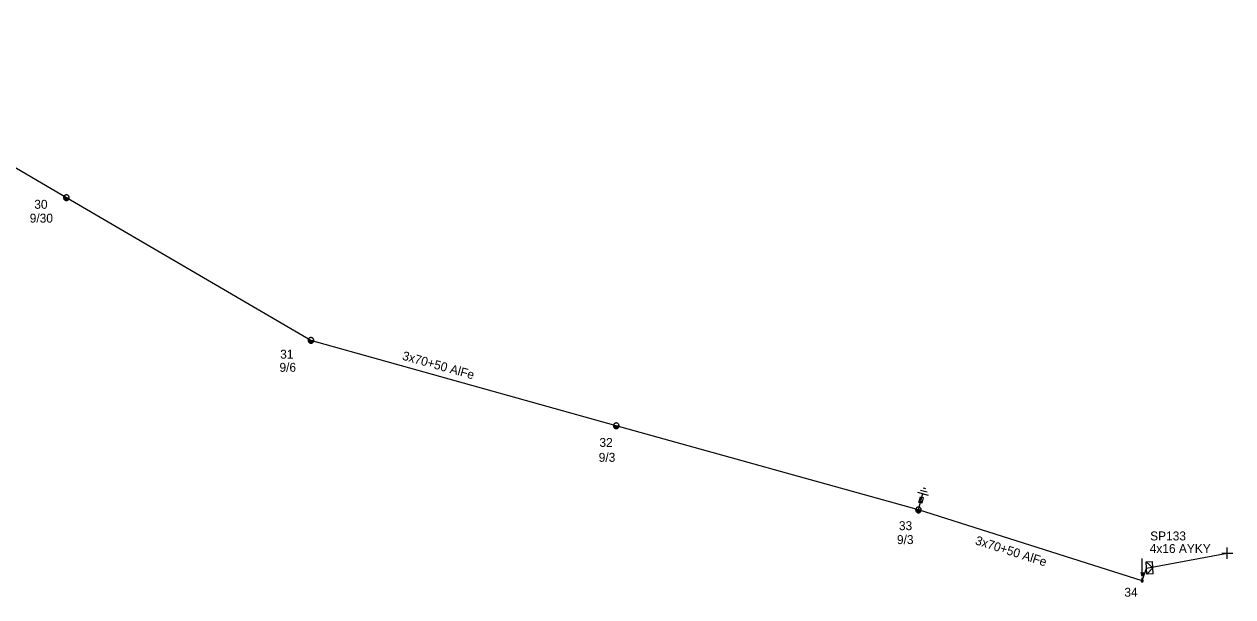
# Model space of a CAD drawing. Extents: x -788458 to -786145, y -1154772 to -1152372.
# Drawn here: x -787317.8 to -787182.3, y -1153011 to -1152946.8 of the extents above; entities that cross this region are included whole.
import ezdxf

# ---------------------------------------------------------------- set-up
doc = ezdxf.new("R2010")
doc.units = 0
for name, color, linetype in [('Vrstva 1', 7, 'Continuous'), ('Vrstva 12', 7, 'Continuous'), ('Vrstva 13', 7, 'Continuous'), ('Vrstva 14', 7, 'Continuous'), ('Vrstva 15', 7, 'Continuous'), ('Vrstva 16', 7, 'Continuous'), ('Vrstva 2', 7, 'Continuous'), ('Vrstva 31', 7, 'Continuous'), ('Vrstva 33', 7, 'Continuous'), ('Vrstva 34', 7, 'Continuous'), ('Vrstva 52', 7, 'Continuous'), ('Vrstva 54', 7, 'Continuous'), ('Vrstva 59', 7, 'Continuous'), ('Vrstva 9', 7, 'Continuous')]:
    doc.layers.add(name, color=color, linetype=linetype)

# ---------------------------------------------------------------- blocks, each defined once
blk = doc.blocks.new('NN440')
at = {"layer": 'Vrstva 2'}
for points in [[(0.63, 0), (0.63, 0.06), (0.62, 0.13), (0.6, 0.19), (0.58, 0.25), (0.55, 0.31), (0.51, 0.37), (0.47, 0.42), (0.42, 0.46), (0.37, 0.51), (0.32, 0.54), (0.26, 0.57), (0.2, 0.59), (0.13, 0.61), (0.07, 0.62), (0, 0.63), (-0.06, 0.62), (-0.13, 0.61), (-0.19, 0.59), (-0.26, 0.57), (-0.31, 0.54), (-0.37, 0.51), (-0.42, 0.46), (-0.47, 0.42), (-0.51, 0.37), (-0.54, 0.31), (-0.57, 0.25), (-0.6, 0.19), (-0.62, 0.13), (-0.63, 0.06), (-0.63, 0), (-0.63, -0.07), (-0.62, -0.14), (-0.6, -0.2), (-0.57, -0.26), (-0.54, -0.32), (-0.51, -0.37), (-0.47, -0.43), (-0.42, -0.47), (-0.37, -0.51), (-0.31, -0.55), (-0.26, -0.58), (-0.19, -0.6), (-0.13, -0.62), (-0.06, -0.63), (0, -0.63), (0.07, -0.63), (0.13, -0.62), (0.2, -0.6), (0.26, -0.58), (0.32, -0.55), (0.37, -0.51), (0.42, -0.47), (0.47, -0.43), (0.51, -0.37), (0.55, -0.32), (0.58, -0.26), (0.6, -0.2), (0.62, -0.14), (0.63, -0.07), (0.63, 0)], [(-0.63, 0), (0.63, 0)], [(-0.6, -0.18), (0.57, -0.18)], [(-0.51, -0.32), (0.5, -0.32)], [(-0.37, -0.47), (0.35, -0.47)]]:
    blk.add_lwpolyline(points, dxfattribs=at)
blk = doc.blocks.new('NN565')
at = {"layer": 'Vrstva 2'}
for points in [[(0.01, 0.53), (0.01, 2.53)], [(0.16, 0.94), (0.01, 0.53), (-0.12, 0.94)]]:
    blk.add_lwpolyline(points, dxfattribs=at)
blk = doc.blocks.new('NN800')
at = {"layer": 'Vrstva 1'}
for points in [[(-0.44, 0.44), (0.44, -0.44)], [(-0.44, -0.44), (0.44, 0.44)]]:
    blk.add_lwpolyline(points, dxfattribs=at)
blk = doc.blocks.new('NN820')
at = {"layer": 'Vrstva 13'}
for points in [[(0, 0), (0, -1.05)], [(-0.16, -0.81), (0.16, -0.81)], [(-0.16, -1.47), (-0.16, -0.81)], [(0, -1.05), (-0.06, -0.93)], [(0, -1.05), (0.06, -0.93)], [(0.16, -0.81), (0.16, -1.47)], [(0.16, -1.47), (-0.16, -1.47)], [(0, -1.47), (0, -1.87)]]:
    blk.add_lwpolyline(points, dxfattribs=at)
blk = doc.blocks.new('NN630')
at = {"layer": 'Vrstva 9'}
for points in [[(0, -0.7), (-0.7, 0)], [(-0.7, -0.7), (-0.7, 0), (0.7, 0), (0.7, -0.7)], [(-0.7, -0.7), (0.7, -0.7)], [(0, -0.7), (0.7, 0)]]:
    blk.add_lwpolyline(points, dxfattribs=at)
blk = doc.blocks.new('NN810')
at = {"layer": 'Vrstva 14'}
for points in [[(0, -0.64), (0, -1.89)], [(0.63, -1.89), (-0.62, -1.89)], [(0.39, -2.2), (-0.4, -2.2)], [(0, -2.52), (-0.12, -2.52)], [(0.14, -2.52), (0, -2.52)]]:
    blk.add_lwpolyline(points, dxfattribs=at)
blk = doc.blocks.new('NN500')
at = {"layer": 'Vrstva 2'}
for points in [[(0, -0.24), (0.02, -0.23), (0.05, -0.23), (0.07, -0.22), (0.09, -0.22), (0.12, -0.2), (0.14, -0.19), (0.16, -0.18), (0.17, -0.16), (0.19, -0.14), (0.2, -0.12), (0.21, -0.1), (0.22, -0.07), (0.23, -0.05), (0.23, -0.02), (0.23, 0), (0.23, 0.02), (0.23, 0.05), (0.22, 0.07), (0.21, 0.1), (0.2, 0.12), (0.19, 0.14), (0.17, 0.16), (0.16, 0.17), (0.14, 0.19), (0.12, 0.2), (0.09, 0.21), (0.07, 0.22), (0.05, 0.23), (0.02, 0.23), (0, 0.23), (-0.03, 0.23), (-0.05, 0.23), (-0.07, 0.22), (-0.1, 0.21), (-0.12, 0.2), (-0.14, 0.19), (-0.16, 0.17), (-0.18, 0.16), (-0.19, 0.14), (-0.2, 0.12), (-0.22, 0.1), (-0.22, 0.07), (-0.23, 0.05), (-0.23, 0.02), (-0.24, 0), (-0.23, -0.02), (-0.23, -0.05), (-0.22, -0.07), (-0.22, -0.1), (-0.2, -0.12), (-0.19, -0.14), (-0.18, -0.16), (-0.16, -0.18), (-0.14, -0.19), (-0.12, -0.2), (-0.1, -0.22), (-0.07, -0.22), (-0.05, -0.23), (-0.03, -0.23), (0, -0.24)], [(0, -0.24), (0.02, -0.23), (0.05, -0.23), (0.07, -0.22), (0.09, -0.22), (0.12, -0.2), (0.14, -0.19), (0.16, -0.18), (0.17, -0.16), (0.19, -0.14), (0.2, -0.12), (0.21, -0.1), (0.22, -0.07), (0.23, -0.05), (0.23, -0.02), (0.23, 0), (0.23, 0.02), (0.23, 0.05), (0.22, 0.07), (0.21, 0.1), (0.2, 0.12), (0.19, 0.14), (0.17, 0.16), (0.16, 0.17), (0.14, 0.19), (0.12, 0.2), (0.09, 0.21), (0.07, 0.22), (0.05, 0.23), (0.02, 0.23), (0, 0.23), (-0.03, 0.23), (-0.05, 0.23), (-0.07, 0.22), (-0.1, 0.21), (-0.12, 0.2), (-0.14, 0.19), (-0.16, 0.17), (-0.18, 0.16), (-0.19, 0.14), (-0.2, 0.12), (-0.22, 0.1), (-0.22, 0.07), (-0.23, 0.05), (-0.23, 0.02), (-0.24, 0), (-0.23, -0.02), (-0.23, -0.05), (-0.22, -0.07), (-0.22, -0.1), (-0.2, -0.12), (-0.19, -0.14), (-0.18, -0.16), (-0.16, -0.18), (-0.14, -0.19), (-0.12, -0.2), (-0.1, -0.22), (-0.07, -0.22), (-0.05, -0.23), (-0.03, -0.23), (0, -0.24)], [(0, -0.21), (0.02, -0.2), (0.04, -0.2), (0.06, -0.2), (0.08, -0.19), (0.1, -0.18), (0.12, -0.17), (0.14, -0.15), (0.15, -0.14), (0.16, -0.12), (0.18, -0.1), (0.19, -0.08), (0.19, -0.06), (0.2, -0.04), (0.2, -0.02), (0.2, 0), (0.2, 0.02), (0.2, 0.04), (0.19, 0.06), (0.19, 0.08), (0.18, 0.1), (0.16, 0.12), (0.15, 0.14), (0.14, 0.15), (0.12, 0.17), (0.1, 0.18), (0.08, 0.19), (0.06, 0.19), (0.04, 0.2), (0.02, 0.2), (0, 0.2), (-0.02, 0.2), (-0.04, 0.2), (-0.06, 0.19), (-0.08, 0.19), (-0.1, 0.18), (-0.12, 0.17), (-0.14, 0.15), (-0.15, 0.14), (-0.17, 0.12), (-0.18, 0.1), (-0.19, 0.08), (-0.2, 0.06), (-0.2, 0.04), (-0.21, 0.02), (-0.21, 0), (-0.21, -0.02), (-0.2, -0.04), (-0.2, -0.06), (-0.19, -0.08), (-0.18, -0.1), (-0.17, -0.12), (-0.15, -0.14), (-0.14, -0.15), (-0.12, -0.17), (-0.1, -0.18), (-0.08, -0.19), (-0.06, -0.2), (-0.04, -0.2), (-0.02, -0.2), (0, -0.21)], [(0, -0.18), (0.02, -0.18), (0.04, -0.17), (0.05, -0.17), (0.07, -0.16), (0.09, -0.15), (0.1, -0.14), (0.12, -0.13), (0.13, -0.12), (0.14, -0.1), (0.15, -0.09), (0.16, -0.07), (0.17, -0.05), (0.17, -0.04), (0.17, -0.02), (0.17, 0), (0.17, 0.02), (0.17, 0.04), (0.17, 0.05), (0.16, 0.07), (0.15, 0.09), (0.14, 0.1), (0.13, 0.12), (0.12, 0.13), (0.1, 0.14), (0.09, 0.15), (0.07, 0.16), (0.05, 0.17), (0.04, 0.17), (0.02, 0.17), (0, 0.18), (-0.02, 0.17), (-0.04, 0.17), (-0.06, 0.17), (-0.07, 0.16), (-0.09, 0.15), (-0.1, 0.14), (-0.12, 0.13), (-0.13, 0.12), (-0.14, 0.1), (-0.15, 0.09), (-0.16, 0.07), (-0.17, 0.05), (-0.17, 0.04), (-0.18, 0.02), (-0.18, 0), (-0.18, -0.02), (-0.17, -0.04), (-0.17, -0.05), (-0.16, -0.07), (-0.15, -0.09), (-0.14, -0.1), (-0.13, -0.12), (-0.12, -0.13), (-0.1, -0.14), (-0.09, -0.15), (-0.07, -0.16), (-0.06, -0.17), (-0.04, -0.17), (-0.02, -0.18), (0, -0.18)], [(0, -0.15), (0.01, -0.15), (0.03, -0.14), (0.04, -0.14), (0.06, -0.13), (0.07, -0.13), (0.08, -0.12), (0.1, -0.11), (0.11, -0.1), (0.12, -0.09), (0.13, -0.07), (0.13, -0.06), (0.14, -0.05), (0.14, -0.03), (0.14, -0.02), (0.14, 0), (0.14, 0.01), (0.14, 0.03), (0.14, 0.04), (0.13, 0.06), (0.13, 0.07), (0.12, 0.09), (0.11, 0.1), (0.1, 0.11), (0.08, 0.12), (0.07, 0.13), (0.06, 0.13), (0.04, 0.14), (0.03, 0.14), (0.01, 0.14), (0, 0.15), (-0.02, 0.14), (-0.03, 0.14), (-0.05, 0.14), (-0.06, 0.13), (-0.07, 0.13), (-0.09, 0.12), (-0.1, 0.11), (-0.11, 0.1), (-0.12, 0.09), (-0.13, 0.07), (-0.13, 0.06), (-0.14, 0.04), (-0.14, 0.03), (-0.15, 0.01), (-0.15, 0), (-0.15, -0.02), (-0.14, -0.03), (-0.14, -0.05), (-0.13, -0.06), (-0.13, -0.07), (-0.12, -0.09), (-0.11, -0.1), (-0.1, -0.11), (-0.09, -0.12), (-0.07, -0.13), (-0.06, -0.13), (-0.05, -0.14), (-0.03, -0.14), (-0.02, -0.15), (0, -0.15)], [(0, -0.12), (0.01, -0.12), (0.02, -0.11), (0.03, -0.11), (0.05, -0.11), (0.06, -0.1), (0.07, -0.09), (0.08, -0.09), (0.09, -0.08), (0.09, -0.07), (0.1, -0.06), (0.11, -0.05), (0.11, -0.04), (0.11, -0.02), (0.11, -0.01), (0.12, 0), (0.11, 0.01), (0.11, 0.02), (0.11, 0.04), (0.11, 0.05), (0.1, 0.06), (0.09, 0.07), (0.09, 0.08), (0.08, 0.09), (0.07, 0.09), (0.06, 0.1), (0.05, 0.11), (0.03, 0.11), (0.02, 0.11), (0.01, 0.12), (0, 0.12), (-0.01, 0.12), (-0.03, 0.11), (-0.04, 0.11), (-0.05, 0.11), (-0.06, 0.1), (-0.07, 0.09), (-0.08, 0.09), (-0.09, 0.08), (-0.1, 0.07), (-0.1, 0.06), (-0.11, 0.05), (-0.11, 0.04), (-0.12, 0.02), (-0.12, 0.01), (-0.12, 0), (-0.12, -0.01), (-0.12, -0.02), (-0.11, -0.04), (-0.11, -0.05), (-0.1, -0.06), (-0.1, -0.07), (-0.09, -0.08), (-0.08, -0.09), (-0.07, -0.09), (-0.06, -0.1), (-0.05, -0.11), (-0.04, -0.11), (-0.03, -0.11), (-0.01, -0.12), (0, -0.12)], [(0, -0.09), (0.01, -0.09), (0.02, -0.09), (0.03, -0.08), (0.03, -0.08), (0.04, -0.08), (0.05, -0.07), (0.06, -0.07), (0.06, -0.06), (0.07, -0.05), (0.07, -0.04), (0.08, -0.04), (0.08, -0.03), (0.08, -0.02), (0.09, -0.01), (0.09, 0), (0.09, 0.01), (0.08, 0.02), (0.08, 0.03), (0.08, 0.03), (0.07, 0.04), (0.07, 0.05), (0.06, 0.06), (0.06, 0.06), (0.05, 0.07), (0.04, 0.07), (0.03, 0.08), (0.03, 0.08), (0.02, 0.08), (0.01, 0.09), (0, 0.09), (-0.01, 0.09), (-0.02, 0.08), (-0.03, 0.08), (-0.04, 0.08), (-0.04, 0.07), (-0.05, 0.07), (-0.06, 0.06), (-0.07, 0.06), (-0.07, 0.05), (-0.08, 0.04), (-0.08, 0.03), (-0.08, 0.03), (-0.09, 0.02), (-0.09, 0.01), (-0.09, 0), (-0.09, -0.01), (-0.09, -0.02), (-0.08, -0.03), (-0.08, -0.04), (-0.08, -0.04), (-0.07, -0.05), (-0.07, -0.06), (-0.06, -0.07), (-0.05, -0.07), (-0.04, -0.08), (-0.04, -0.08), (-0.03, -0.08), (-0.02, -0.09), (-0.01, -0.09), (0, -0.09)], [(0, -0.06), (0, -0.06), (0.01, -0.06), (0.02, -0.05), (0.02, -0.05), (0.03, -0.05), (0.03, -0.05), (0.04, -0.04), (0.04, -0.04), (0.05, -0.03), (0.05, -0.03), (0.05, -0.02), (0.05, -0.02), (0.05, -0.01), (0.06, -0.01), (0.06, 0), (0.06, 0.01), (0.05, 0.01), (0.05, 0.02), (0.05, 0.02), (0.05, 0.03), (0.05, 0.03), (0.04, 0.04), (0.04, 0.04), (0.03, 0.05), (0.03, 0.05), (0.02, 0.05), (0.02, 0.05), (0.01, 0.06), (0, 0.06), (0, 0.06), (-0.01, 0.06), (-0.01, 0.06), (-0.02, 0.05), (-0.02, 0.05), (-0.03, 0.05), (-0.03, 0.05), (-0.04, 0.04), (-0.04, 0.04), (-0.05, 0.03), (-0.05, 0.03), (-0.05, 0.02), (-0.06, 0.02), (-0.06, 0.01), (-0.06, 0.01), (-0.06, 0), (-0.06, -0.01), (-0.06, -0.01), (-0.06, -0.02), (-0.05, -0.02), (-0.05, -0.03), (-0.05, -0.03), (-0.04, -0.04), (-0.04, -0.04), (-0.03, -0.05), (-0.03, -0.05), (-0.02, -0.05), (-0.02, -0.05), (-0.01, -0.06), (-0.01, -0.06), (0, -0.06)], [(0, -0.03), (0, -0.03), (0, -0.03), (0.01, -0.03), (0.01, -0.03), (0.01, -0.02), (0.02, -0.02), (0.02, -0.02), (0.02, -0.02), (0.02, -0.02), (0.02, -0.01), (0.02, -0.01), (0.03, -0.01), (0.03, -0.01), (0.03, 0), (0.03, 0), (0.03, 0), (0.03, 0.01), (0.03, 0.01), (0.02, 0.01), (0.02, 0.01), (0.02, 0.02), (0.02, 0.02), (0.02, 0.02), (0.02, 0.02), (0.01, 0.02), (0.01, 0.02), (0.01, 0.03), (0, 0.03), (0, 0.03), (0, 0.03), (0, 0.03), (-0.01, 0.03), (-0.01, 0.03), (-0.01, 0.02), (-0.02, 0.02), (-0.02, 0.02), (-0.02, 0.02), (-0.02, 0.02), (-0.02, 0.02), (-0.03, 0.01), (-0.03, 0.01), (-0.03, 0.01), (-0.03, 0.01), (-0.03, 0), (-0.03, 0), (-0.03, 0), (-0.03, -0.01), (-0.03, -0.01), (-0.03, -0.01), (-0.03, -0.01), (-0.02, -0.02), (-0.02, -0.02), (-0.02, -0.02), (-0.02, -0.02), (-0.02, -0.02), (-0.01, -0.03), (-0.01, -0.03), (-0.01, -0.03), (0, -0.03), (0, -0.03)], [(0.23, 0), (0.7, 0)]]:
    blk.add_lwpolyline(points, dxfattribs=at)

msp = doc.modelspace()

# ---------------------------------------------------------------- linework, layer by layer
at = {"layer": 'Vrstva 1'}
msp.add_lwpolyline([(-787192.48, -1153009.24), (-787217.55, -1153001.28), (-787251.42, -1152991.85), (-787285.63, -1152982.28), (-787313.04, -1152966.29), (-787346.23, -1152946.84)], dxfattribs=at)
at = {"layer": 'Vrstva 52'}
msp.add_lwpolyline([(-787192.48, -1153009.24), (-787191.98, -1153007.8)], dxfattribs=at)
at = {"layer": 'Vrstva 59'}
msp.add_lwpolyline([(-787191.98, -1153007.8), (-787182.94, -1153006.13)], dxfattribs=at)

# ---------------------------------------------------------------- block references
at = {"layer": 'Vrstva 13', "xscale": 0.5, "yscale": 0.5}
for p in [(-787313.04, -1152966.29), (-787285.63, -1152982.28), (-787251.42, -1152991.85), (-787217.55, -1153001.28)]:
    msp.add_blockref('NN440', p, dxfattribs=at)
at = {"layer": 'Vrstva 13'}
msp.add_blockref('NN565', (-787192.48, -1153009.24), dxfattribs=at)
at = {"layer": 'Vrstva 13', "xscale": 0.5, "yscale": 0.5, "rotation": 90}
msp.add_blockref('NN500', (-787192.48, -1153009.24), dxfattribs=at)
at = {"layer": 'Vrstva 15', "rotation": 164.44186801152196}
msp.add_blockref('NN810', (-787217.55, -1153001.28), dxfattribs=at)
at = {"layer": 'Vrstva 16', "rotation": 164.44186801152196}
msp.add_blockref('NN820', (-787217.55, -1153001.28), dxfattribs=at)
at = {"layer": 'Vrstva 31', "rotation": 93.14809608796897}
msp.add_blockref('NN630', (-787191.98, -1153007.8), dxfattribs=at)
at = {"layer": 'Vrstva 34', "rotation": 44.99999995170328}
msp.add_blockref('NN800', (-787182.94, -1153006.13), dxfattribs=at)

# ---------------------------------------------------------------- texts
at = {"layer": 'Vrstva 12'}
for s, p in [('9/30', (-787317.15, -1152969.08)), ('9/6', (-787289.16, -1152985.8)), ('9/3', (-787253.38, -1152995.89)), ('9/3', (-787219.96, -1153005.11))]:
    msp.add_text(s, height=1, dxfattribs=at).set_placement(p)
at = {"layer": 'Vrstva 14'}
for s, p in [('30', (-787316.64, -1152967.53)), ('31', (-787289.08, -1152984.33)), ('32', (-787253.3, -1152994.22)), ('33', (-787219.74, -1153003.55)), ('34', (-787194.47, -1153011.01))]:
    msp.add_text(s, height=1, dxfattribs=at).set_placement(p)
at = {"layer": 'Vrstva 2'}
for rotation, p in [(344.371, (-787275.47, -1152984.43)), (342.385, (-787211.26, -1153005.12))]:
    msp.add_text('3x70+50 AlFe', height=1, rotation=rotation, dxfattribs=at).set_placement(p)
at = {"layer": 'Vrstva 33'}
msp.add_text('SP133', height=1, dxfattribs=at).set_placement((-787191.58, -1153004.7))
at = {"layer": 'Vrstva 54'}
msp.add_text('4x16 AYKY', height=1, dxfattribs=at).set_placement((-787191.63, -1153006.11))

doc.saveas('drawing.dxf')
